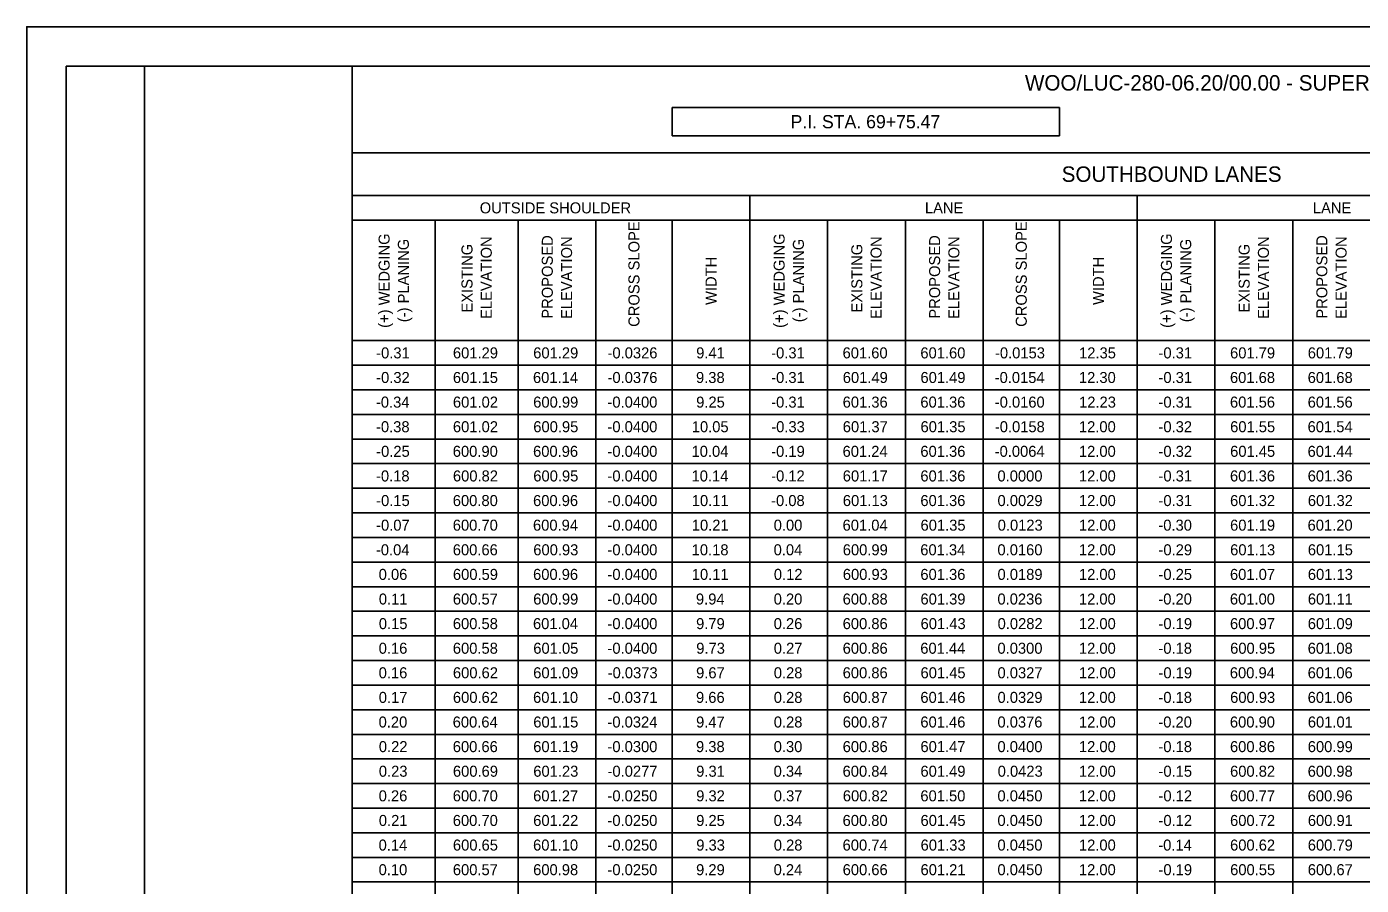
# Model space of a CAD drawing. Extents: x 0 to 34, y 0 to 22.
# Drawn here: x 0 to 16.97, y 11.08 to 22 of the extents above; entities that cross this region are included whole.
import ezdxf

# ---------------------------------------------------------------- set-up
doc = ezdxf.new("R2010")
doc.units = 0
for name, color, linetype in [('SH_Border', 7, 'Continuous'), ('SH_Cut_Line', 7, 'Continuous'), ('SH_Text', 7, 'Continuous')]:
    doc.layers.add(name, color=color, linetype=linetype)

msp = doc.modelspace()

# ---------------------------------------------------------------- linework, layer by layer
at = {"layer": 'SH_Border'}
for points in [[(0.5, 21.5), (1.5, 21.5), (1.5, 0.5), (0.5, 0.5)], [(1.5, 21.5), (33.5, 21.5), (33.5, 0.5), (1.5, 0.5)]]:
    msp.add_lwpolyline(points, close=True, dxfattribs=at)
at = {"layer": 'SH_Cut_Line'}
msp.add_lwpolyline([(0, 0), (34, 0), (34, 22), (0, 22)], close=True, dxfattribs=at)
at = {"layer": 'SH_Text'}
for p, q in [((4.14, 21.5), (29.356, 21.5)), ((4.14, 21.5), (4.14, 0.484)), ((8.208, 20.973), (13.133, 20.973)), ((8.208, 20.973), (8.208, 20.611)), ((13.133, 20.973), (13.133, 20.611)), ((8.208, 20.611), (13.133, 20.611)), ((4.14, 20.396), (29.356, 20.396)), ((4.14, 19.853), (29.356, 19.853)), ((9.196, 19.853), (9.196, 0.484)), ((14.121, 19.853), (14.121, 0.484)), ((4.14, 19.54), (24.942, 19.54)), ((5.194, 19.54), (5.194, 0.484)), ((6.248, 19.54), (6.248, 0.484)), ((7.236, 19.54), (7.236, 0.484)), ((8.208, 19.54), (8.208, 0.484)), ((10.185, 19.54), (10.185, 0.484)), ((11.173, 19.54), (11.173, 0.484)), ((12.161, 19.54), (12.161, 0.484)), ((13.133, 19.54), (13.133, 0.484)), ((15.109, 19.54), (15.109, 0.484)), ((16.098, 19.54), (16.098, 0.484)), ((4.14, 18.008), (29.356, 18.008)), ((4.14, 17.695), (29.356, 17.695)), ((4.14, 17.382), (29.356, 17.382)), ((4.14, 17.069), (29.356, 17.069)), ((4.14, 16.756), (29.356, 16.756)), ((4.14, 16.444), (29.356, 16.444)), ((4.14, 16.131), (29.356, 16.131)), ((4.14, 15.818), (29.356, 15.818)), ((4.14, 15.505), (29.356, 15.505)), ((4.14, 15.192), (29.356, 15.192)), ((4.14, 14.879), (29.356, 14.879)), ((4.14, 14.566), (29.356, 14.566)), ((4.14, 14.253), (29.356, 14.253)), ((4.14, 13.94), (29.356, 13.94)), ((4.14, 13.627), (29.356, 13.627)), ((4.14, 13.314), (29.356, 13.314)), ((4.14, 13.001), (29.356, 13.001)), ((4.14, 12.688), (29.356, 12.688)), ((4.14, 12.375), (29.356, 12.375)), ((4.14, 12.062), (29.356, 12.062)), ((4.14, 11.749), (29.356, 11.749)), ((4.14, 11.436), (29.356, 11.436)), ((4.14, 11.124), (29.356, 11.124))]:
    msp.add_line(p, q, dxfattribs=at)

# ---------------------------------------------------------------- texts
for s, height, p in [('WOO/LUC-280-06.20/00.00 - SUPERELEVATION TABLE', 0.196, (12.694, 21.188)), ('P.I. STA. 69+75.47', 0.168, (9.713, 20.708)), ('SOUTHBOUND LANES', 0.196, (13.161, 20.027)), ('OUTSIDE SHOULDER', 0.14, (5.761, 19.626)), ('LANE', 0.14, (11.422, 19.626)), ('LANE', 0.14, (16.355, 19.626)), ('-0.31', 0.14, (4.444, 17.782)), ('601.29', 0.14, (5.42, 17.782)), ('601.29', 0.14, (6.441, 17.782)), ('-0.0326', 0.14, (7.386, 17.782)), ('9.41', 0.14, (8.513, 17.782)), ('-0.31', 0.14, (9.467, 17.782)), ('601.60', 0.14, (10.375, 17.782)), ('601.60', 0.14, (11.364, 17.782)), ('-0.0153', 0.14, (12.313, 17.782)), ('12.35', 0.14, (13.382, 17.782)), ('-0.31', 0.14, (14.392, 17.782)), ('601.79', 0.14, (15.302, 17.782)), ('601.79', 0.14, (16.29, 17.782)), ('-0.32', 0.14, (4.444, 17.469)), ('601.15', 0.14, (5.42, 17.469)), ('601.14', 0.14, (6.438, 17.469)), ('-0.0376', 0.14, (7.386, 17.469)), ('9.38', 0.14, (8.511, 17.469)), ('-0.31', 0.14, (9.467, 17.469)), ('601.49', 0.14, (10.377, 17.469)), ('601.49', 0.14, (11.365, 17.469)), ('-0.0154', 0.14, (12.309, 17.469)), ('12.30', 0.14, (13.38, 17.469)), ('-0.31', 0.14, (14.392, 17.469)), ('601.68', 0.14, (15.301, 17.469)), ('601.68', 0.14, (16.289, 17.469)), ('-0.34', 0.14, (4.441, 17.156)), ('601.02', 0.14, (5.42, 17.156)), ('600.99', 0.14, (6.441, 17.156)), ('-0.0400', 0.14, (7.385, 17.156)), ('9.25', 0.14, (8.513, 17.156)), ('-0.31', 0.14, (9.467, 17.156)), ('601.36', 0.14, (10.376, 17.156)), ('601.36', 0.14, (11.364, 17.156)), ('-0.0160', 0.14, (12.31, 17.156)), ('12.23', 0.14, (13.382, 17.156)), ('-0.31', 0.14, (14.392, 17.156)), ('601.56', 0.14, (15.301, 17.156)), ('601.56', 0.14, (16.289, 17.156)), ('-0.38', 0.14, (4.442, 16.843)), ('601.02', 0.14, (5.42, 16.843)), ('600.95', 0.14, (6.442, 16.843)), ('-0.0400', 0.14, (7.385, 16.843)), ('10.05', 0.14, (8.457, 16.843)), ('-0.33', 0.14, (9.468, 16.843)), ('601.37', 0.14, (10.377, 16.843)), ('601.35', 0.14, (11.366, 16.843)), ('-0.0158', 0.14, (12.311, 16.843)), ('12.00', 0.14, (13.38, 16.843)), ('-0.32', 0.14, (14.392, 16.843)), ('601.55', 0.14, (15.303, 16.843)), ('601.54', 0.14, (16.288, 16.843)), ('-0.25', 0.14, (4.444, 16.53)), ('600.90', 0.14, (5.418, 16.53)), ('600.96', 0.14, (6.439, 16.53)), ('-0.0400', 0.14, (7.385, 16.53)), ('10.04', 0.14, (8.454, 16.53)), ('-0.19', 0.14, (9.467, 16.53)), ('601.24', 0.14, (10.375, 16.53)), ('601.36', 0.14, (11.364, 16.53)), ('-0.0064', 0.14, (12.309, 16.53)), ('12.00', 0.14, (13.38, 16.53)), ('-0.32', 0.14, (14.392, 16.53)), ('601.45', 0.14, (15.303, 16.53)), ('601.44', 0.14, (16.288, 16.53)), ('-0.18', 0.14, (4.442, 16.217)), ('600.82', 0.14, (5.42, 16.217)), ('600.95', 0.14, (6.442, 16.217)), ('-0.0400', 0.14, (7.385, 16.217)), ('10.14', 0.14, (8.454, 16.217)), ('-0.12', 0.14, (9.467, 16.217)), ('601.17', 0.14, (10.377, 16.217)), ('601.36', 0.14, (11.364, 16.217)), ('0.0000', 0.14, (12.344, 16.217)), ('12.00', 0.14, (13.38, 16.217)), ('-0.31', 0.14, (14.392, 16.217)), ('601.36', 0.14, (15.301, 16.217)), ('601.36', 0.14, (16.289, 16.217)), ('-0.15', 0.14, (4.444, 15.904)), ('600.80', 0.14, (5.418, 15.904)), ('600.96', 0.14, (6.439, 15.904)), ('-0.0400', 0.14, (7.385, 15.904)), ('10.11', 0.14, (8.457, 15.904)), ('-0.08', 0.14, (9.466, 15.904)), ('601.13', 0.14, (10.378, 15.904)), ('601.36', 0.14, (11.364, 15.904)), ('0.0029', 0.14, (12.345, 15.904)), ('12.00', 0.14, (13.38, 15.904)), ('-0.31', 0.14, (14.392, 15.904)), ('601.32', 0.14, (15.302, 15.904)), ('601.32', 0.14, (16.291, 15.904)), ('-0.07', 0.14, (4.443, 15.591)), ('600.70', 0.14, (5.418, 15.591)), ('600.94', 0.14, (6.438, 15.591)), ('-0.0400', 0.14, (7.385, 15.591)), ('10.21', 0.14, (8.457, 15.591)), ('0.00', 0.14, (9.499, 15.591)), ('601.04', 0.14, (10.375, 15.591)), ('601.35', 0.14, (11.366, 15.591)), ('0.0123', 0.14, (12.347, 15.591)), ('12.00', 0.14, (13.38, 15.591)), ('-0.30', 0.14, (14.39, 15.591)), ('601.19', 0.14, (15.302, 15.591)), ('601.20', 0.14, (16.288, 15.591)), ('-0.04', 0.14, (4.441, 15.278)), ('600.66', 0.14, (5.418, 15.278)), ('600.93', 0.14, (6.442, 15.278)), ('-0.0400', 0.14, (7.385, 15.278)), ('10.18', 0.14, (8.456, 15.278)), ('0.04', 0.14, (9.498, 15.278)), ('600.99', 0.14, (10.377, 15.278)), ('601.34', 0.14, (11.363, 15.278)), ('0.0160', 0.14, (12.344, 15.278)), ('12.00', 0.14, (13.38, 15.278)), ('-0.29', 0.14, (14.392, 15.278)), ('601.13', 0.14, (15.303, 15.278)), ('601.15', 0.14, (16.291, 15.278)), ('0.06', 0.14, (4.476, 14.965)), ('600.59', 0.14, (5.42, 14.965)), ('600.96', 0.14, (6.439, 14.965)), ('-0.0400', 0.14, (7.385, 14.965)), ('10.11', 0.14, (8.457, 14.965)), ('0.12', 0.14, (9.501, 14.965)), ('600.93', 0.14, (10.378, 14.965)), ('601.36', 0.14, (11.364, 14.965)), ('0.0189', 0.14, (12.345, 14.965)), ('12.00', 0.14, (13.38, 14.965)), ('-0.25', 0.14, (14.392, 14.965)), ('601.07', 0.14, (15.301, 14.965)), ('601.13', 0.14, (16.291, 14.965)), ('0.11', 0.14, (4.478, 14.652)), ('600.57', 0.14, (5.419, 14.652)), ('600.99', 0.14, (6.441, 14.652)), ('-0.0400', 0.14, (7.385, 14.652)), ('9.94', 0.14, (8.51, 14.652)), ('0.20', 0.14, (9.499, 14.652)), ('600.88', 0.14, (10.376, 14.652)), ('601.39', 0.14, (11.365, 14.652)), ('0.0236', 0.14, (12.344, 14.652)), ('12.00', 0.14, (13.38, 14.652)), ('-0.20', 0.14, (14.39, 14.652)), ('601.00', 0.14, (15.3, 14.652)), ('601.11', 0.14, (16.291, 14.652)), ('0.15', 0.14, (4.478, 14.339)), ('600.58', 0.14, (5.419, 14.339)), ('601.04', 0.14, (6.438, 14.339)), ('-0.0400', 0.14, (7.385, 14.339)), ('9.79', 0.14, (8.512, 14.339)), ('0.26', 0.14, (9.499, 14.339)), ('600.86', 0.14, (10.376, 14.339)), ('601.43', 0.14, (11.367, 14.339)), ('0.0282', 0.14, (12.346, 14.339)), ('12.00', 0.14, (13.38, 14.339)), ('-0.19', 0.14, (14.392, 14.339)), ('600.97', 0.14, (15.301, 14.339)), ('601.09', 0.14, (16.29, 14.339)), ('0.16', 0.14, (4.476, 14.026)), ('600.58', 0.14, (5.419, 14.026)), ('601.05', 0.14, (6.442, 14.026)), ('-0.0400', 0.14, (7.385, 14.026)), ('9.73', 0.14, (8.514, 14.026)), ('0.27', 0.14, (9.5, 14.026)), ('600.86', 0.14, (10.376, 14.026)), ('601.44', 0.14, (11.363, 14.026)), ('0.0300', 0.14, (12.344, 14.026)), ('12.00', 0.14, (13.38, 14.026)), ('-0.18', 0.14, (14.391, 14.026)), ('600.95', 0.14, (15.303, 14.026)), ('601.08', 0.14, (16.289, 14.026)), ('0.16', 0.14, (4.476, 13.714)), ('600.62', 0.14, (5.42, 13.714)), ('601.09', 0.14, (6.441, 13.714)), ('-0.0373', 0.14, (7.388, 13.714)), ('9.67', 0.14, (8.512, 13.714)), ('0.28', 0.14, (9.5, 13.714)), ('600.86', 0.14, (10.376, 13.714)), ('601.45', 0.14, (11.366, 13.714)), ('0.0327', 0.14, (12.345, 13.714)), ('12.00', 0.14, (13.38, 13.714)), ('-0.19', 0.14, (14.392, 13.714)), ('600.94', 0.14, (15.299, 13.714)), ('601.06', 0.14, (16.289, 13.714)), ('0.17', 0.14, (4.477, 13.401)), ('600.62', 0.14, (5.42, 13.401)), ('601.10', 0.14, (6.439, 13.401)), ('-0.0371', 0.14, (7.387, 13.401)), ('9.66', 0.14, (8.511, 13.401)), ('0.28', 0.14, (9.5, 13.401)), ('600.87', 0.14, (10.377, 13.401)), ('601.46', 0.14, (11.364, 13.401)), ('0.0329', 0.14, (12.345, 13.401)), ('12.00', 0.14, (13.38, 13.401)), ('-0.18', 0.14, (14.391, 13.401)), ('600.93', 0.14, (15.303, 13.401)), ('601.06', 0.14, (16.289, 13.401)), ('0.20', 0.14, (4.475, 13.088)), ('600.64', 0.14, (5.417, 13.088)), ('601.15', 0.14, (6.442, 13.088)), ('-0.0324', 0.14, (7.385, 13.088)), ('9.47', 0.14, (8.512, 13.088)), ('0.28', 0.14, (9.5, 13.088)), ('600.87', 0.14, (10.377, 13.088)), ('601.46', 0.14, (11.364, 13.088)), ('0.0376', 0.14, (12.344, 13.088)), ('12.00', 0.14, (13.38, 13.088)), ('-0.20', 0.14, (14.39, 13.088)), ('600.90', 0.14, (15.3, 13.088)), ('601.01', 0.14, (16.291, 13.088)), ('0.22', 0.14, (4.478, 12.775)), ('600.66', 0.14, (5.418, 12.775)), ('601.19', 0.14, (6.441, 12.775)), ('-0.0300', 0.14, (7.385, 12.775)), ('9.38', 0.14, (8.511, 12.775)), ('0.30', 0.14, (9.499, 12.775)), ('600.86', 0.14, (10.376, 12.775)), ('601.47', 0.14, (11.365, 12.775)), ('0.0400', 0.14, (12.344, 12.775)), ('12.00', 0.14, (13.38, 12.775)), ('-0.18', 0.14, (14.391, 12.775)), ('600.86', 0.14, (15.301, 12.775)), ('600.99', 0.14, (16.29, 12.775)), ('0.23', 0.14, (4.478, 12.462)), ('600.69', 0.14, (5.42, 12.462)), ('601.23', 0.14, (6.442, 12.462)), ('-0.0277', 0.14, (7.386, 12.462)), ('9.31', 0.14, (8.513, 12.462)), ('0.34', 0.14, (9.498, 12.462)), ('600.84', 0.14, (10.375, 12.462)), ('601.49', 0.14, (11.365, 12.462)), ('0.0423', 0.14, (12.347, 12.462)), ('12.00', 0.14, (13.38, 12.462)), ('-0.15', 0.14, (14.392, 12.462)), ('600.82', 0.14, (15.302, 12.462)), ('600.98', 0.14, (16.289, 12.462)), ('0.26', 0.14, (4.476, 12.149)), ('600.70', 0.14, (5.418, 12.149)), ('601.27', 0.14, (6.44, 12.149)), ('-0.0250', 0.14, (7.385, 12.149)), ('9.32', 0.14, (8.513, 12.149)), ('0.37', 0.14, (9.5, 12.149)), ('600.82', 0.14, (10.378, 12.149)), ('601.50', 0.14, (11.364, 12.149)), ('0.0450', 0.14, (12.344, 12.149)), ('12.00', 0.14, (13.38, 12.149)), ('-0.12', 0.14, (14.392, 12.149)), ('600.77', 0.14, (15.301, 12.149)), ('600.96', 0.14, (16.289, 12.149)), ('0.21', 0.14, (4.478, 11.836)), ('600.70', 0.14, (5.418, 11.836)), ('601.22', 0.14, (6.441, 11.836)), ('-0.0250', 0.14, (7.385, 11.836)), ('9.25', 0.14, (8.513, 11.836)), ('0.34', 0.14, (9.498, 11.836)), ('600.80', 0.14, (10.375, 11.836)), ('601.45', 0.14, (11.366, 11.836)), ('0.0450', 0.14, (12.344, 11.836)), ('12.00', 0.14, (13.38, 11.836)), ('-0.12', 0.14, (14.392, 11.836)), ('600.72', 0.14, (15.302, 11.836)), ('600.91', 0.14, (16.291, 11.836)), ('0.14', 0.14, (4.475, 11.523)), ('600.65', 0.14, (5.42, 11.523)), ('601.10', 0.14, (6.439, 11.523)), ('-0.0250', 0.14, (7.385, 11.523)), ('9.33', 0.14, (8.514, 11.523)), ('0.28', 0.14, (9.5, 11.523)), ('600.74', 0.14, (10.375, 11.523)), ('601.33', 0.14, (11.367, 11.523)), ('0.0450', 0.14, (12.344, 11.523)), ('12.00', 0.14, (13.38, 11.523)), ('-0.14', 0.14, (14.389, 11.523)), ('600.62', 0.14, (15.302, 11.523)), ('600.79', 0.14, (16.29, 11.523)), ('0.10', 0.14, (4.475, 11.21)), ('600.57', 0.14, (5.419, 11.21)), ('600.98', 0.14, (6.44, 11.21)), ('-0.0250', 0.14, (7.385, 11.21)), ('9.29', 0.14, (8.512, 11.21)), ('0.24', 0.14, (9.498, 11.21)), ('600.66', 0.14, (10.376, 11.21)), ('601.21', 0.14, (11.366, 11.21)), ('0.0450', 0.14, (12.344, 11.21)), ('12.00', 0.14, (13.38, 11.21)), ('-0.19', 0.14, (14.392, 11.21)), ('600.55', 0.14, (15.303, 11.21)), ('600.67', 0.14, (16.29, 11.21))]:
    msp.add_text(s, height=height, dxfattribs=at).set_placement(p)
for s, p in [('CROSS SLOPE', (7.792, 18.183)), ('CROSS SLOPE', (12.717, 18.183)), ('(+) WEDGING', (4.615, 18.17)), ('(+) WEDGING', (9.638, 18.17)), ('(+) WEDGING', (14.563, 18.17)), ('(-) PLANING', (4.86, 18.242)), ('EXISTING ', (5.669, 18.365)), ('ELEVATION', (5.914, 18.283)), ('PROPOSED ', (6.69, 18.287)), ('ELEVATION', (6.935, 18.283)), ('(-) PLANING', (9.883, 18.242)), ('EXISTING ', (10.626, 18.365)), ('ELEVATION', (10.871, 18.283)), ('PROPOSED ', (11.615, 18.287)), ('ELEVATION', (11.86, 18.283)), ('(-) PLANING', (14.808, 18.242)), ('EXISTING ', (15.551, 18.365)), ('ELEVATION', (15.796, 18.283)), ('PROPOSED ', (16.539, 18.287)), ('ELEVATION', (16.784, 18.283)), ('WIDTH', (8.772, 18.461)), ('WIDTH', (13.697, 18.461))]:
    msp.add_text(s, height=0.14, rotation=90, dxfattribs=at).set_placement(p)

doc.saveas('drawing.dxf')
